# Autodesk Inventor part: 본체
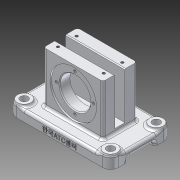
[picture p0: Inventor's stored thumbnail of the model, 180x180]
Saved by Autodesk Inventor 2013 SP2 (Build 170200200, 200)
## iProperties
Created: 2025-04
Part Number: 본체
Material: 알루미늄 6061
Document SubType Name: Modeling
Designer: 601
Density: 2.71 g/cm^3
Mass: 495.463 g
Surface Area: 444.005 cm^2
Volume: 182.827 cm^3
Author: 601
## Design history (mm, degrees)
sketch "스케치1"
  geometry: L1 (-35, 30)-(35, 30); L2 (35, 30)-(35, -42); L3 (35, -42)-(-35, -42); L4 (-35, -42)-(-35, 30); 2 further points
  constraints: 8 end point, 2 parallel, 1 horizontal, 1 midpoint, 1 perpendicular, 1 vertical alignment
  dimensions: "d0" = 72 distance between parallel lines of L3 L1; "d2" = 42 distance from line of L3 point (0, 0); "d3" = 70 distance of L2.end L3.end
extrude "돌출1" new body sketch "스케치1" stored distance "d4" = 40; taper "d5" = 0 deg
sketch "스케치2"
  geometry: L1 (-25, 16)-(95, 16); L2 (95, 16)-(95, -56); L3 (95, -56)-(-25, -56); L4 (-25, -56)-(-25, 16); L5 (-25, 16)-(95, -56); L6 (95, 16)-(-25, -56); 1 further point
  constraints: 12 end point, 2 midpoint, 2 parallel, 1 horizontal, 1 perpendicular
  dimensions: "d6" = 72 distance of L1.end L2.end; "d8" = 120 distance of L2.end L3.end
extrude "돌출2" join sketch "스케치2" distance "d9" = 12; taper "d10" = 0 deg
fillet "모깎기1" dims "d11" = 9
sketch "스케치3"
  geometry: L1 (0, 0)-(54, 0) reference; L2 (11, 5)-(43, 5); L3 (43, 5)-(43, 0); L4 (43, 0)-(11, 0); L5 (11, 0)-(11, 5); 2 further points
  constraints: 8 end point, 2 midpoint, 2 parallel, 1 horizontal, 1 perpendicular
  dimensions: "d12" = 32 distance between parallel lines of L3 L5; "d14" = 5 distance between parallel lines of L1 L2
extrude "돌출3" cut sketch "스케치3" stored distance "d15" = 12; taper "d16" = 0 deg
sketch "스케치4"
  geometry: L1 (0, 0)-(40, 0) reference; L2 (14, 0)-(26, 0); L3 (26, 0)-(26, -55); L4 (26, -55)-(14, -55); L5 (14, -55)-(14, 0); 2 further points
  constraints: 8 end point, 2 midpoint, 2 parallel, 1 horizontal, 1 perpendicular
  dimensions: "d17" = 12 distance between parallel lines of L3 L5; "d19" = 55 distance between parallel lines of L4 L1
extrude "돌출4" cut sketch "스케치4" stored distance "d20" = 12; taper "d21" = 0 deg
sketch "스케치5"
  geometry: C1 r 8 at (-16, 47); A1 r 9 centre (-16, 47) between (-16, 56) and (-25, 47) reference; 1 further point
  constraints: 1 centre point, 1 coincident
  dimensions: "d22" = 16 diameter of C1
extrude "돌출5" join sketch "스케치5" distance "d23" = 3; taper "d24" = 0 deg
sketch "스케치6"
  geometry: C1 r 8 at (0, 0) reference; C2 r 4.5 at (0, 0); 1 further point
  constraints: 1 centre point, 1 coincident
  dimensions: "d25" = 9 diameter of C2
extrude "돌출6" cut sketch "스케치6" distance "d26" = 15; taper "d27" = 0 deg
sketch "스케치7"
  geometry: C1 r 17 at (0, 0); 1 further point
  constraints: 1 centre point, 1 coincident
  dimensions: "d28" = 34 diameter of C1
extrude "돌출7" join sketch "스케치7" distance "d29" = 7; taper "d30" = 0 deg
sketch "스케치8"
  geometry: C1 r 27.5 at (0, 0); 1 further point
  constraints: 1 centre point, 1 coincident
  dimensions: "d31" = 55 diameter of C1
extrude "돌출8" cut sketch "스케치8" distance "d32" = 2; taper "d33" = 0 deg
sketch "스케치9"
  geometry: C1 r 27.5 at (0, 0) reference; C2 r 18 at (0, 0)
  constraints: 1 centre point, 1 coincident
  dimensions: "d34" = 36 diameter of C2
extrude "돌출9" cut sketch "스케치9" stored distance "d35" = 36 (= d34); taper "d36" = 0 deg
sketch "스케치10"
  geometry: C1 r 17 at (0, 0) reference; C2 r 11 at (0, 0)
  constraints: 1 centre point, 1 coincident
  dimensions: "d37" = 22 diameter of C2
extrude "돌출10" cut sketch "스케치10" stored distance "d38" = 2; taper "d39" = 0 deg
sketch "스케치11"
  geometry: C1 r 11 at (-35, 25) reference; C2 r 15 at (-35, 25)
  constraints: 1 centre point, 1 coincident
  dimensions: "d40" = 30 diameter of C2
extrude "돌출11" cut sketch "스케치11" distance "d41" = 5; taper "d42" = 0 deg
chamfer "모따기1" distance "d43" = 1; stored, may be unused: second distance "d44" = 2, angle "d45" = 45 deg
sketch "스케치12" dims "d46" = 44
  geometry: C1 r 19 at (0, 0) reference; 2 further points
  constraints: 2 vertical alignment, 1 coincident, 2 other
hole "구멍1" sketch "스케치12" at (0, 22) diameter "d47" = 3.242; stored, may be unused: countersink angle "d51" = 90 deg, drill point angle "d53" = 118 deg; dims "d48" = 8, "d49" = 4, "d50" = 2, "d52" = 10
fillet "모깎기2" dims "d57" = 3
chamfer "모따기2" distance "d58" = 1; stored, may be unused: second distance "d59" = 2, angle "d60" = 45 deg
fillet "모깎기3" dims "d61" = 3
fillet "모깎기4" dims "d62" = 3
fillet "모깎기5" dims "d63" = 3
fillet "모깎기6" dims "d64" = 3
sketch "스케치13"
  geometry: L1 (59, -31)-(5, -31); L2 (5, -31)-(5, -9); L3 (5, -9)-(59, -9); L4 (59, -9)-(59, -31); L5 (59, -31)-(5, -9); L6 (5, -31)-(59, -9); 5 further points
  constraints: 12 end point, 4 coincident, 2 midpoint, 2 parallel, 1 horizontal, 1 perpendicular
  dimensions: "d65" = 54 distance between parallel lines of L4 L2; "d67" = 22 distance between parallel lines of L1 L3
hole "구멍2" sketch "스케치13" at (5, -9), (59, -9), (59, -31), (5, -31) diameter "d68" = 3.242; stored, may be unused: countersink angle "d72" = 90 deg, drill point angle "d74" = 118 deg; dims "d69" = 8, "d70" = 4, "d71" = 2, "d73" = 10
node "작업 평면1"
sketch "스케치14"
  geometry: L1 (111, 0)-(102, 0) reference; 2 further points
  constraints: 1 vertical alignment, 1 other
  dimensions: "d76" = 5 distance from line of L1 point (51, 5)
feature "엠보싱1" sketch "스케치14" dims "d0" = 72, "d2" = 42, "d3" = 70, "d77" = 0.5, "d78" = 0
fillet "모깎기7" dims "d79" = 3
fillet "모깎기8" dims "d80" = 3
node "솔리드1"
mirror "대칭1"
mirror "대칭2"
pattern_circular "원형 패턴1" dims angle "d55" = 360 deg
other parameters: "d75" = 8.25
